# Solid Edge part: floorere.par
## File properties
Author: Deepak Maini
Template: normal.par
Last saved by: CADCIM
Revision: 6
Application: Solid Edge
Accuracy: 0.99
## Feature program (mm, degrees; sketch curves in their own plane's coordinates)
sketch for "unnamed Protrusion 1" plane through (0, 0, 18.8714) normal (0, 0, 1) x-axis (1, 0, 0)
  line (-106.7153, 22.606) -> (-36.8209, 22.606)
  arc centre (-20.2938, 18.624) radius 17 from (-36.8209, 22.606) to (-36.6443, 13.97) cw
  line (-36.6443, 13.97) -> (-106.7153, 13.97)
  line (-106.7153, 13.97) -> (-106.7153, 22.606)
extrude "unnamed Protrusion 1" add finite 8.5604 along +normal
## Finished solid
Body 1: solid body, 6 faces, 12 edges, 8 vertices.
  Faces by surface: plane 5, cylinder 1
  Edges by curve: line 10, circle 2
Bounding box of the edges (mm): 103.421 x 34.000 x 8.560, from (-106.7153, 1.624, 18.8714) to (-3.2938, 35.624, 27.4319).
Cylindrical faces by radius (mm): R17 x1
Planar faces by outward normal: +y 1, +z 1, -x 1, -y 1, -z 1
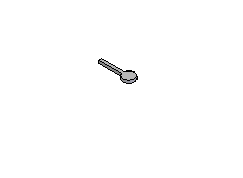
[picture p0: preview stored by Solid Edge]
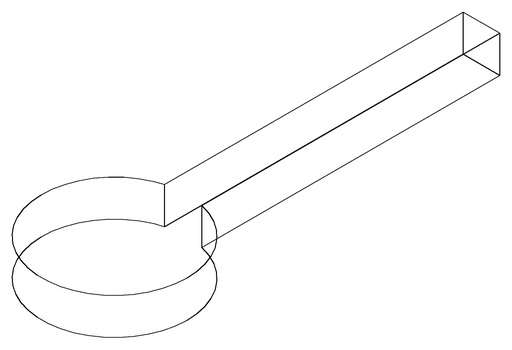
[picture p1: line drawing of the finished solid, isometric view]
